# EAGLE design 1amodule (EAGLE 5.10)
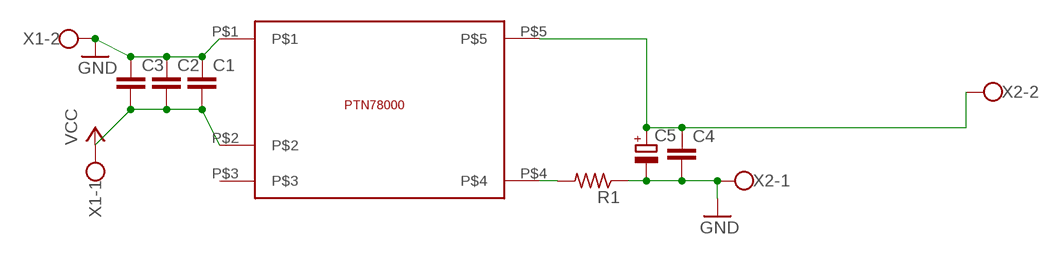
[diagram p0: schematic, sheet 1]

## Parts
C1  C-EUC1206  [C1206]
C2  C-EUC1206  [C1206]
C3  C-EUC1206  [C1206]
C4  C-EUC1206  [C1206]
C5  CPOL-EUE5-6  [E5-6]
R1  R-US_0207/10  [0207/10]
U$1  1.5APOWERMODULE  [1.5APOWERMODULE]
X1  W237-102  [W237-102]
X2  W237-102  [W237-102]

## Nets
GND: C1.1 C2.1 C3.1 C4.2 C5.- R1.1 U$1.P$1 X1.2 X2.1
N$1: R1.2 U$1.P$4
N$2: C4.1 C5.+ U$1.P$5 X2.2
VCC: C1.2 C2.2 C3.2 U$1.P$2 X1.1
Unconnected: U$1.P$3

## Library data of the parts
C1-C4 = rcl:C-EU: CAPACITOR, European symbol
C5 = rcl:CPOL-EU: POLARIZED CAPACITOR, European symbol
R1 = rcl:R-US_: RESISTOR, American symbol
U$1 = TIPOWERMODULE:1.5APOWERMODULE
X1 X2 = con-wago-500:W237-102: WAGO SCREW CLAMP

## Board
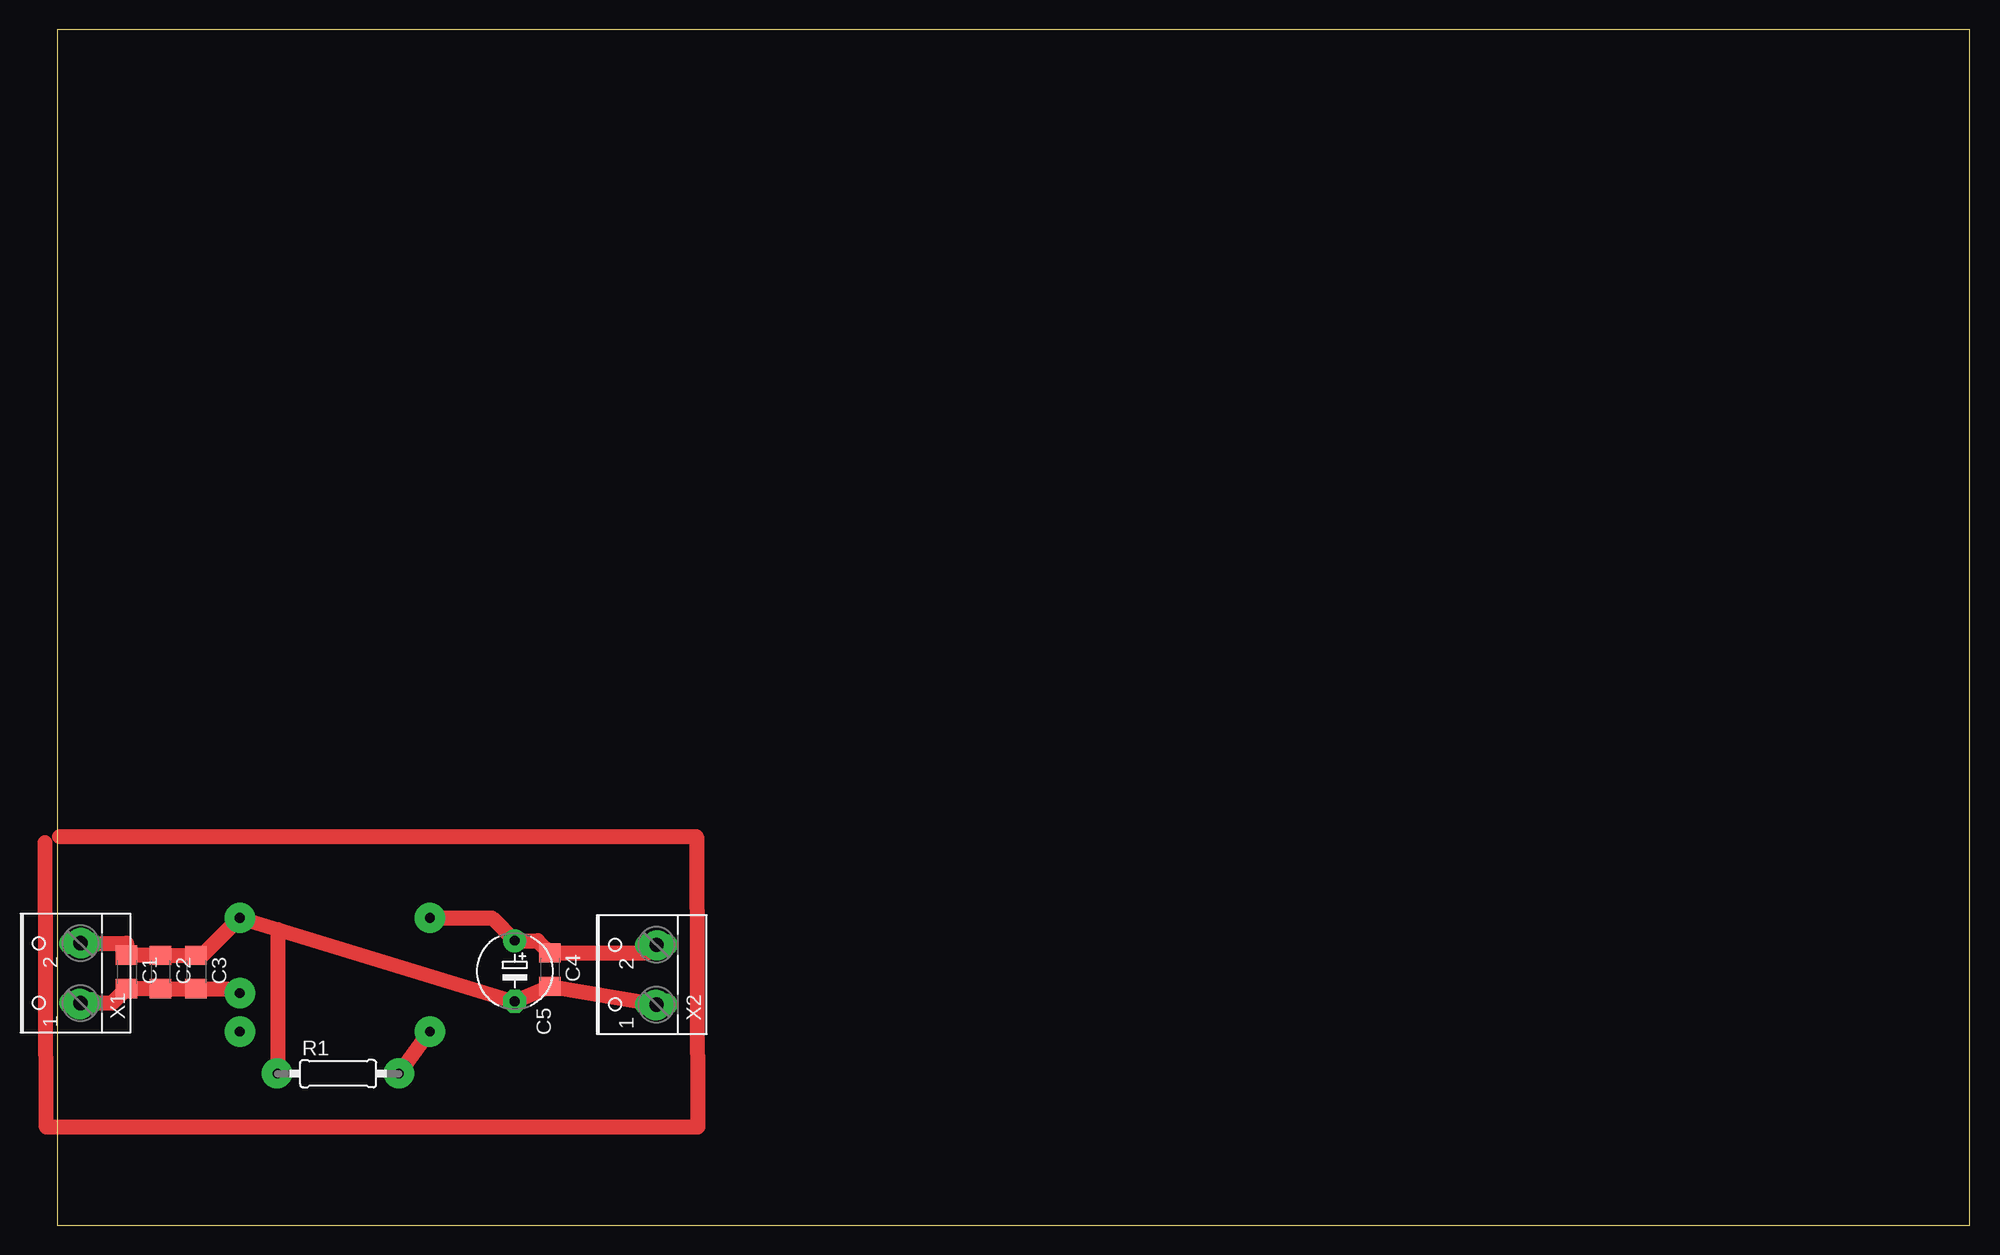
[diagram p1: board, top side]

Size 160 x 100 mm. Coordinates in mm from the lower left corner, seen from the top.
Outline: 0,0 160,0 160,100 0,100 0,0
Copper layers (1*16): Top 0.035mm / dielectric 1.5mm / Bottom 0.035mm
Design rules "default": minimum track width 10mil, minimum drill 24mil, track to track 8mil, track to pad 8mil, pad to pad 8mil, via to via 8mil, smd to smd 8mil, copper to edge 40mil, drill to drill 8mil, minimum pad ring 10mil, minimum via ring 8mil, stop-mask expansion 4mil, vias tented up to drill 0mil, thermal gap 10mil

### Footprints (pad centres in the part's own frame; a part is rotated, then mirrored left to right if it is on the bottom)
C1206 = smd 1.6 x 1.8: 1 -1.4,0; 2 1.4,0
E5-6 = drill 0.813 pad 1.905 round: + -2.54,0 | drill 0.813 pad 1.905 octagon: - 2.54,0
0207/10 = drill 0.813 octagon: 1 -5.08,0; 2 5.08,0
1.5APOWERMODULE = drill 0.8 pad 2.184 round: P$1 0,0; P$2 0,-6.3; P$3 0,-9.5; P$4 15.9,-9.5; P$5 15.9,0
W237-102 = drill 1.194 long: 1 -2.5,-1.27; 2 2.5,-1.27

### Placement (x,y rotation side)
C1  5.82,21.19 270 top
C2  8.65,21.18 270 top
C3  11.64,21.18 270 top
C4  41.23,21.38 270 top
C5  38.29,21.25 270 top
R1  23.52,12.67 0 top
U$1  15.28,25.7 0 top
X1  0.69,21.08 90 top
X2  48.88,20.95 90 top

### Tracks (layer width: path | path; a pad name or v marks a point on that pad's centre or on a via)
GND
  Top 1.27: X1.2 5.82,23.58 C1.1 C2.1 C3.1 12.16,22.58 U$1.P$1 18.47,24.73 | 18.47,24.73 37.78,18.86 C5.- C4.2 X2.1 | 18.47,24.73 R1.1
N$1
  Top 1.27: U$1.P$4 R1.2
N$2  (via drill 0.6 pad 2.54)
  Top 1.27: U$1.P$5 v31.2,25.7 36.38,25.7 C5.+ 40.22,23.79 C4.1 49.48,22.78 X2.2
N$3
  Top 1.27: 0.2,32.5 53.5,32.5 53.6,8.2 -0.9,8.2 -1,32
N$4  (via drill 0.6 pad 2.54)
  other vias: 18.4,12.7
N$5  (via drill 0.6 pad 2.54)
  other vias: 28.6,12.7
N$6  (via drill 0.6 pad 2.54)
  other vias: 2,23.6
N$7  (via drill 0.6 pad 2.54)
  other vias: 1.9,18.5
N$8  (via drill 0.6 pad 2.54)
  other vias: 50.2,23.4
N$9  (via drill 0.6 pad 2.54)
  other vias: 50.1,18.4
N$10  (via drill 0.6 pad 2.54)
  other vias: 15.3,25.7
N$11  (via drill 0.6 pad 2.54)
  other vias: 15.3,19.4
N$12  (via drill 0.6 pad 2.54)
  other vias: 15.3,16.2
N$13  (via drill 0.6 pad 2.54)
  other vias: 31.2,16.2
VCC
  Top 1.27: X1.1 4.61,18.58 C1.2 C2.2 C3.2 14.9,19.78 U$1.P$2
